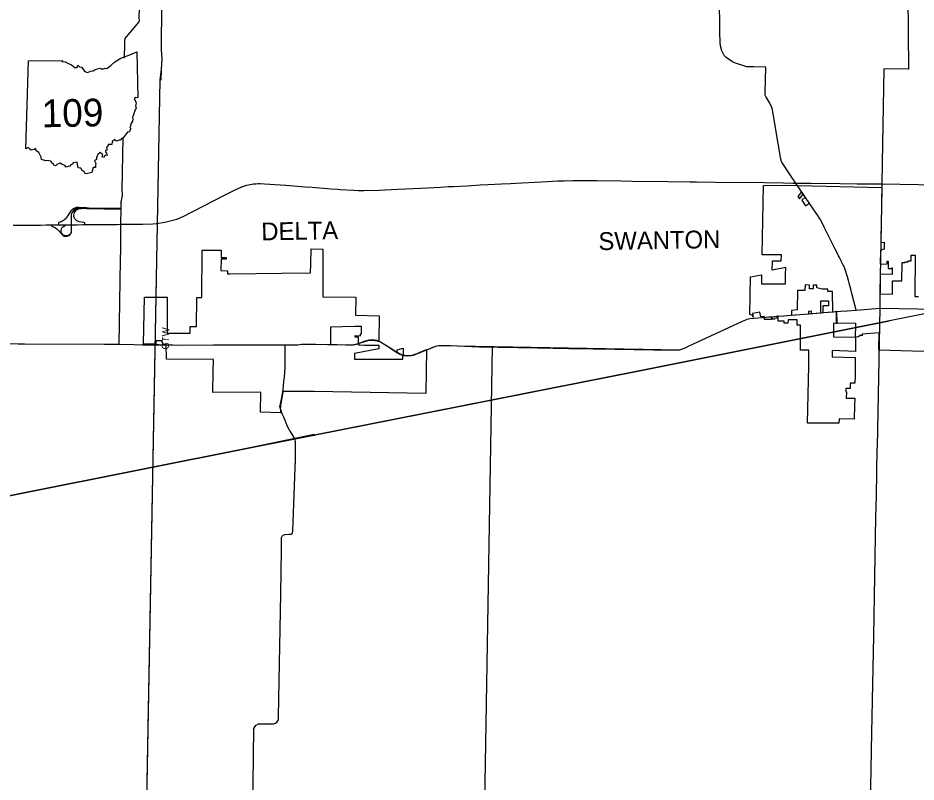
# Model space of a CAD drawing. Extents: x 0 to 849, y 0 to 440.
# Drawn here: x 399.3 to 566.7, y 72.4 to 214.9 of the extents above; entities that cross this region are included whole.
import ezdxf

# ---------------------------------------------------------------- set-up
doc = ezdxf.new("R2010")
doc.units = 0
for name, color, linetype in [('DV_X_Corp_Line', 7, 'Continuous'), ('GM_X_Corporation_Text', 7, 'Continuous'), ('GM_X_County', 7, 'Continuous'), ('GM_X_Interchange_Ramps', 7, 'Continuous'), ('GM_X_Interstate_Route', 7, 'Continuous'), ('PV_P_Walk', 7, 'Continuous'), ('RD_X_RR_2', 7, 'Continuous'), ('SH_Data', 7, 'Continuous')]:
    doc.layers.add(name, color=color, linetype=linetype)

msp = doc.modelspace()

# ---------------------------------------------------------------- linework, layer by layer
at = {"layer": 'DV_X_Corp_Line'}
msp.add_lwpolyline([(568.24, 152.7), (563.91, 152.84), (559.78, 152.94), (559.85, 156.15), (556.66, 155.91), (556.66, 155.63), (556.44, 155.74), (555.9, 155.41), (555.46, 155.4), (555.51, 157.6), (555.51, 157.65), (555.52, 157.94), (551.35, 157.98), (551.32, 155.45), (555.46, 155.4), (555.41, 152.7), (551.08, 152.87), (551.07, 152.28), (551.06, 151.71), (555.39, 151.59), (555.34, 148.1), (555.32, 146.79), (554.42, 146.79), (554.42, 145.79), (553.62, 145.8), (553.6, 145.2), (553.73, 145.19), (553.7, 143.99), (555.28, 143.99), (555.25, 142.68), (555.21, 140.1), (552.36, 140.14), (552.35, 139.36), (546.47, 139.36), (546.73, 150.01), (546.76, 152.92), (545.17, 152.96), (545.2, 157.62), (544.56, 157.61), (544.56, 158.58), (542.85, 158.59), (542.83, 157.98), (542.13, 158), (542.15, 158.35), (541.02, 158.38), (541.02, 159.28), (540.76, 159.26), (540.76, 158.89), (540.35, 158.86), (540.35, 158.71), (539.93, 158.7), (539.93, 159.11), (539.77, 159.11), (539.77, 158.64), (538.47, 158.66), (538.47, 159.25), (537.81, 159.19), (537.57, 160.01), (536.91, 159.91), (536.2, 159.78), (536.34, 159.13), (536.16, 159.46), (535.72, 159.62), (535.85, 166.59), (537.91, 167.01), (537.9, 165.34), (542.35, 165.3), (542.37, 165.81), (542.4, 167.08), (542.43, 168.34), (539.89, 167.84), (539.95, 169.59), (541.6, 169.59), (541.63, 170.72), (538.05, 170.73), (538.29, 183.67), (542.56, 183.71), (542.56, 183.69), (544.72, 183.64), (560.34, 183.27), (560.14, 173.05), (560.78, 173.06), (560.78, 171.77), (560.11, 171.62), (560.06, 168.98), (561.31, 169.02), (561.31, 169.52), (561.53, 169.53), (561.53, 168.17), (562.22, 168.16), (562.22, 168.27), (562.26, 168.27), (562.26, 167.06), (560.03, 167.1), (559.96, 163.42), (562.31, 163.38), (562.32, 165.9), (564.1, 165.9), (564.14, 169.3), (564.68, 169.3), (564.68, 169.41), (565.28, 169.42), (565.28, 169.59), (565.79, 169.59), (565.8, 170.66), (566.53, 170.67), (566.48, 162.95), (567.15, 162.94)], dxfattribs=at)
for points in [[(545.38, 182.48), (544.68, 181.62), (544.97, 181.19), (545.69, 182.03)], [(546.07, 181.46), (545.4, 180.92), (546.09, 179.88), (546.83, 180.35)], [(462.77, 154.2), (462.78, 155.35), (462.12, 155.36), (462.13, 155.68), (463.12, 155.65), (463.14, 155.99), (463.32, 155.99), (463.35, 157.33), (462.16, 157.36), (462.07, 157.36), (457.55, 157.23), (457.52, 154.03), (458.75, 154), (460.63, 153.92), (461.98, 154.01), (462.12, 154.03), (462.72, 154.1), (462.81, 153.95), (462.99, 153.95), (463.01, 153.93), (463.04, 153.93), (463.91, 153.91), (466.53, 153.88), (466.56, 153.19), (462, 152.31), (462.01, 151.26), (471.03, 151.28), (471.03, 152.03), (470.43, 152.27), (470.1, 152.43), (469.97, 152.5), (469.97, 153.02), (471.08, 153.31), (471.07, 152.05), (471.27, 152.01), (471.58, 151.96), (471.92, 151.94), (472.35, 151.95), (472.59, 151.98), (472.99, 152.07), (473.29, 152.16), (474.28, 152.55), (475.47, 153.05), (475.35, 144.89), (457.99, 145.18), (454.5, 145.25), (448.7, 145.23), (448.63, 144.78), (448.49, 144.07), (448.28, 143.03), (448.24, 142.78), (448.21, 142.54), (448.2, 142.32), (448.19, 142.1), (448.21, 141.77), (448.24, 141.55), (448.3, 141.28), (444.47, 141.41), (444.55, 145.11), (435.6, 145.07), (435.69, 148.91), (435.72, 151.18), (426.95, 151.28), (426.94, 154.02), (426.39, 154.02), (426.05, 154.72), (425.01, 154.71), (424.99, 154.04), (422.69, 154.06), (422.89, 162.8), (427.07, 162.81), (427.08, 156.13), (431.41, 156.13), (431.41, 157.37), (432.56, 157.37), (432.65, 162.79), (433.57, 162.76), (433.61, 171.61), (437.19, 171.56), (437.16, 170.2), (438.1, 170.21), (438.11, 169.91), (437.18, 169.9), (437.09, 167.79), (438.35, 167.76), (438.35, 167.17), (438.86, 167.16), (448.42, 167.33), (453.83, 167.37), (453.87, 169), (453.92, 171.81), (456.12, 171.78), (456.11, 162.88), (462.26, 162.85), (462.2, 159.46), (466.63, 159.37), (466.55, 154.62), (466.55, 154.62), (466.39, 154.67), (466.18, 154.73), (466.02, 154.76), (465.8, 154.8), (465.58, 154.82), (465.36, 154.83), (465.14, 154.83), (464.92, 154.82), (464.7, 154.8), (464.49, 154.76), (464.27, 154.71), (464.06, 154.65), (463.75, 154.55), (463.18, 154.34)], [(543.49, 159.48), (546.71, 159.74), (546.7, 160.25), (547.15, 160.3), (547.17, 159.78), (548.96, 159.92), (548.96, 162.16), (550.39, 162.16), (550.39, 161.24), (549.36, 161.24), (549.33, 159.95), (551.21, 160.09), (551.15, 163.87), (550.26, 163.88), (550.26, 164.3), (549.23, 164.35), (548.48, 164.52), (548.23, 164.54), (548.24, 165.07), (547.55, 165.08), (547.54, 164.38), (546.86, 164.39), (546.87, 165.09), (546.02, 165.11), (546, 164.05), (544.62, 164.07), (544.56, 160.44), (543.49, 160.33)], [(551.81, 160.14), (551.81, 158.01), (551.99, 158.01), (551.98, 160.16)]]:
    msp.add_lwpolyline(points, close=True, dxfattribs=at)
at = {"layer": 'GM_X_County'}
msp.add_lwpolyline([(565.21, 219.21), (565.34, 205.31), (565.22, 205.31), (560.72, 205.39), (560.73, 205.24), (560.42, 187.96), (560.42, 187.92), (560.35, 183.93), (560.28, 180.21), (560.26, 179.01), (560.23, 177.46), (560.2, 175.92), (560.18, 174.37), (560.13, 171.84), (560.11, 170.74), (560.1, 170.09), (560.04, 166.44), (559.94, 160.75), (559.44, 135.01), (559.44, 134.96), (559.43, 134.51), (559.27, 125.86), (559.19, 121.81), (558.76, 99.7), (558.41, 81.63), (558.09, 64.89)], dxfattribs=at)
at = {"layer": 'GM_X_Interchange_Ramps'}
for points in [[(405.52, 176.31), (405.53, 176.04), (405.68, 176.01), (406.01, 175.89), (406.29, 175.73), (406.55, 175.54), (406.76, 175.32), (407.5, 174.51), (407.73, 174.31), (407.92, 174.22), (408.16, 174.16), (408.41, 174.17), (408.65, 174.24), (408.83, 174.34), (409.04, 174.52), (409.15, 174.71), (409.23, 174.91), (409.28, 175.13), (409.27, 175.86), (409.26, 176.34), (409.26, 177.87), (409.27, 178.19), (409.35, 178.45), (409.47, 178.69), (409.61, 178.88), (409.8, 179.07), (409.98, 179.19), (410.22, 179.3), (410.49, 179.38), (410.74, 179.4), (411.08, 179.4), (412.08, 179.38), (418.44, 179.26), (418.52, 179.26)], [(412, 179.46), (412, 179.49), (410.65, 179.57), (410.36, 179.57), (410.13, 179.52), (409.86, 179.42), (409.65, 179.32), (409.47, 179.2), (409.31, 179.08), (409.14, 178.9), (409, 178.72), (408.36, 177.73), (408.22, 177.55), (408.06, 177.39), (407.91, 177.24), (407.74, 177.11), (407.54, 176.98), (407.33, 176.87), (407.12, 176.79), (406.88, 176.73), (406.84, 176.72), (406.84, 176.32)], [(418.52, 179.36), (418.42, 179.36), (412.44, 179.45), (412, 179.46), (410.7, 179.48), (410.36, 179.43), (410.15, 179.36), (409.94, 179.25), (409.73, 179.11), (409.55, 178.93), (409.42, 178.75), (409.31, 178.54), (409.22, 178.29), (409.17, 178.04), (409.17, 177.79), (409.19, 176.34), (409.2, 175.19), (409.17, 174.92), (409.08, 174.72), (408.95, 174.54), (408.78, 174.4), (408.58, 174.3), (408.38, 174.24), (408.17, 174.24), (407.93, 174.3), (407.73, 174.41), (407.57, 174.56), (407.46, 174.71), (407.36, 174.9), (407.32, 175.1), (407.32, 175.34), (407.37, 175.52), (407.48, 175.74), (407.63, 175.92), (407.82, 176.05), (408, 176.13), (408.1, 176.15), (408.1, 176.33)], [(411.76, 176.36), (411.76, 176.71), (411.62, 176.72), (411.11, 176.8), (410.71, 176.89), (410.44, 176.97), (410.26, 177.07), (410.07, 177.22), (409.89, 177.44), (409.78, 177.66), (409.72, 177.88), (409.71, 178.1), (409.73, 178.35), (409.8, 178.59), (409.93, 178.82), (410.06, 178.98), (410.21, 179.11), (410.38, 179.22), (410.61, 179.32), (410.78, 179.35), (411.08, 179.35), (411.08, 179.4)]]:
    msp.add_lwpolyline(points, dxfattribs=at)
at = {"layer": 'GM_X_Interstate_Route'}
for p, q in [((560.35, 183.93), (571.18, 183.73)), ((559.94, 160.75), (578.12, 160.49))]:
    msp.add_line(p, q, dxfattribs=at)
for points in [[(419.15, 207.4), (419.18, 210.2), (419.2, 210.64), (419.29, 211.02), (419.53, 211.37), (421.58, 213.8), (421.8, 214.1), (421.91, 214.4), (421.9, 214.92), (421.92, 216.72), (421.89, 219.36)], [(530.16, 212.32), (530.11, 214.87), (530.08, 216.27), (530.04, 218.98)], [(536.45, 205.76), (535.17, 205.79), (532.85, 206.54), (532.52, 206.69), (531.31, 207.48), (530.94, 207.89), (530.51, 208.78), (530.26, 209.66), (530.19, 210.23), (530.16, 212.32), (530.16, 212.32)], [(543.56, 185.16), (543.38, 185.42), (541.68, 187.98), (541.63, 188.1), (541.49, 188.56), (540.47, 194.78), (539.93, 197.84), (539.86, 198.2), (539.48, 198.99), (538.7, 200.24), (538.61, 200.46), (538.56, 200.93), (538.7, 205.71), (536.45, 205.76), (536.45, 205.76)], [(418.69, 181.41), (418.69, 181.41), (418.75, 181.99), (418.72, 182.81), (418.9, 192.6)], [(418.48, 176.42), (419.23, 176.42), (422.47, 176.44), (424.43, 176.5), (425.12, 176.56), (426.68, 176.78), (428.88, 177.4), (430.18, 177.95), (431.48, 178.6), (431.88, 178.79), (437.81, 181.83), (439.8, 182.86), (441.01, 183.4), (441.93, 183.69), (442.57, 183.83), (443.2, 183.93), (443.72, 183.98), (444.06, 184.01), (444.44, 184), (445.24, 183.98), (448.14, 183.75), (449.19, 183.68), (452.84, 183.4), (454.13, 183.31), (457.64, 183.05), (458.91, 182.94), (459.38, 182.91), (461.91, 182.76), (462.7, 182.73), (463.79, 182.7), (466.64, 182.76), (467.7, 182.81), (470.16, 182.95), (474.39, 183.16), (478.08, 183.35), (479.49, 183.43), (480.48, 183.47), (483.01, 183.6), (485.47, 183.75), (486.88, 183.81), (489.43, 183.94), (491.11, 184.03), (493.23, 184.13), (495.67, 184.26), (498.02, 184.38), (499.9, 184.49), (501.12, 184.54), (502.7, 184.59), (505, 184.57), (506.41, 184.55), (507.19, 184.55), (511.73, 184.49), (513.81, 184.47), (520.42, 184.39), (524.58, 184.34), (524.98, 184.34), (525.77, 184.33), (529.3, 184.29), (538.46, 184.18), (541.99, 184.14), (543.74, 184.11), (544.28, 184.1)], [(543.92, 184.63), (543.61, 185.09), (543.56, 185.16)], [(544.48, 183.8), (544.28, 184.1), (543.98, 184.54), (543.92, 184.63)], [(544.28, 184.1), (545.16, 184.1), (547.09, 184.07), (552.55, 184.01), (555.72, 183.97), (558.01, 183.95), (560.35, 183.93)], [(545.29, 182.61), (544.55, 183.71), (544.48, 183.8)], [(545.6, 182.16), (545.29, 182.61)], [(418.48, 176.42), (418.52, 179.26), (418.52, 179.36), (418.53, 179.48), (418.5, 180.27), (418.52, 180.53), (418.54, 180.67), (418.59, 180.88)], [(418.59, 180.88), (418.66, 181.13), (418.69, 181.41)], [(546, 181.57), (545.6, 182.16)], [(547.02, 180.07), (546, 181.57)], [(548.73, 177.53), (548.4, 178.03), (547.55, 179.3), (547.02, 180.07)], [(551.25, 172.54), (549.6, 175.85), (549, 177.07), (548.95, 177.17), (548.88, 177.31), (548.73, 177.53)], [(398.36, 176.25), (400.9, 176.28), (403.46, 176.28), (404.52, 176.3), (405.22, 176.3), (405.52, 176.31), (406.84, 176.32), (408.1, 176.33), (408.8, 176.33), (409.19, 176.34), (409.26, 176.34), (409.61, 176.34)], [(409.61, 176.34), (410.33, 176.34), (411.38, 176.35), (411.76, 176.36), (413, 176.36), (413.56, 176.37), (414.86, 176.39), (415.85, 176.39), (417.79, 176.4), (418.48, 176.42)], [(418.4, 169.79), (418.44, 171.72), (418.48, 176.42)], [(551.64, 171.78), (551.64, 171.78), (551.25, 172.54)], [(553.23, 168.65), (553.22, 168.65), (552.84, 169.42), (552.81, 169.48), (552.42, 170.25), (552.28, 170.52), (552.18, 170.72), (552.17, 170.75), (551.64, 171.78)], [(418.14, 154.05), (418.4, 169.79)], [(553.46, 168.17), (553.23, 168.65)], [(554.11, 165.95), (554.11, 165.95), (553.94, 166.59), (553.47, 168.16), (553.46, 168.17)], [(555.55, 160.43), (555.15, 162.11), (554.77, 163.52), (554.62, 164.05), (554.24, 165.46), (554.11, 165.95)], [(553.86, 160.3), (553.86, 160.3), (555.55, 160.43), (559.94, 160.75)], [(520.42, 152.99), (522.39, 152.96), (522.71, 153), (523.66, 153.41), (524.32, 153.71), (534.34, 158.33), (535, 158.61), (535.21, 158.7), (535.74, 158.85), (538.78, 159.1)], [(538.78, 159.1), (539.3, 159.14)], [(539.3, 159.14), (539.82, 159.18), (540.84, 159.26)], [(540.84, 159.26), (541.09, 159.28), (541.09, 159.28)], [(541.09, 159.28), (542.09, 159.37), (543.3, 159.46)], [(543.3, 159.46), (545.9, 159.68), (546.68, 159.74), (546.9, 159.76), (546.91, 159.76)], [(546.91, 159.76), (547.41, 159.8), (547.42, 159.8)], [(547.42, 159.8), (549.11, 159.93), (549.11, 159.93)], [(549.11, 159.93), (549.45, 159.96), (549.45, 159.96)], [(549.45, 159.96), (551.31, 160.1), (551.31, 160.1)], [(551.31, 160.1), (551.65, 160.13), (551.65, 160.13)], [(551.65, 160.13), (551.82, 160.14), (551.82, 160.14)], [(551.82, 160.14), (552.64, 160.21), (553.81, 160.3), (553.86, 160.3)], [(388.53, 154.24), (399.3, 154.12), (400.49, 154.11), (415.39, 154.05), (418.14, 154.05), (420.96, 154)], [(450.99, 153.97), (451.46, 153.97), (452.17, 154.09), (452.47, 154.09), (452.92, 154.09), (453.6, 154.09), (454.27, 154.08), (454.77, 154.09), (456.98, 154.02), (457.85, 154.01)], [(461.93, 154), (462.09, 154.02), (462.91, 154.23), (463.7, 154.52), (464.33, 154.74), (464.96, 154.86), (465.73, 154.82), (466.27, 154.71), (466.88, 154.48), (468.46, 153.48)], [(420.96, 154), (422.49, 153.96), (422.9, 153.96)], [(422.9, 153.96), (424.83, 153.94)], [(424.83, 153.94), (426.24, 153.93)], [(426.24, 153.93), (426.77, 153.93), (426.77, 153.93)], [(426.77, 153.93), (428.18, 153.92)], [(428.18, 153.92), (429.33, 153.91), (435.75, 153.92)], [(435.75, 153.92), (438.05, 153.92), (440.45, 153.92)], [(440.45, 153.92), (440.71, 153.92), (441.91, 153.92), (442.36, 153.92)], [(442.36, 153.92), (443.76, 153.94)], [(443.76, 153.94), (444.61, 153.94), (445.76, 153.95), (446.83, 153.96), (446.85, 153.96)], [(446.85, 153.96), (446.85, 153.96), (447.02, 153.96), (447.84, 153.96), (449.12, 153.97)], [(448.95, 147.99), (448.95, 147.99), (449.07, 149.67), (449.11, 151.79), (449.12, 152.51), (449.12, 152.55), (449.12, 153.97)], [(449.12, 153.97), (450.76, 153.97), (450.99, 153.97)], [(457.85, 154.01), (458.78, 153.99), (460.38, 153.96), (461.76, 153.97), (461.93, 154)], [(468.46, 153.48), (469.01, 153.14), (470.02, 152.48), (470.1, 152.43)], [(470.1, 152.43), (470.5, 152.21), (471.13, 151.93), (471.22, 151.93)], [(471.22, 151.93), (471.94, 151.89), (472.56, 151.93), (473.05, 152.03), (474.11, 152.46), (475.15, 152.89), (475.59, 153.07)], [(475.59, 153.07), (475.81, 153.16), (476.6, 153.49), (476.9, 153.59), (477.35, 153.73), (477.69, 153.8), (479.94, 153.81)], [(479.94, 153.81), (485.2, 153.56), (488.81, 153.51), (496.15, 153.39), (501.92, 153.29)], [(501.92, 153.29), (501.92, 153.29), (506.53, 153.21), (510.57, 153.14), (517.79, 153.03)], [(517.79, 153.03), (520.42, 152.99), (520.42, 152.99)], [(448.69, 145.19), (448.75, 145.57), (448.87, 147.08), (448.95, 147.99)], [(448.56, 141.11), (448.35, 141.62), (448.15, 142.21), (448.12, 142.42), (448.28, 143.19), (448.63, 144.8), (448.69, 145.19), (448.69, 145.19)], [(448.83, 140.46), (448.56, 141.1), (448.56, 141.11)], [(449.91, 138.05), (449.91, 138.06), (449.54, 138.7), (448.83, 140.46)], [(451, 131.75), (451, 131.75), (451.02, 132.67), (451.03, 135.89), (450.97, 136.23), (450.88, 136.38), (450.76, 136.65), (449.96, 137.96), (449.91, 138.05)], [(449.72, 118.62), (450.04, 118.62), (450.25, 118.65), (450.47, 118.83), (450.51, 119.29), (451.02, 132.67)], [(442.56, 42.75), (442.94, 65.58), (443.12, 72.11), (443.28, 82.45), (443.42, 82.76), (443.66, 83.03), (444.11, 83.29), (446.92, 83.27), (447.31, 83.42), (447.52, 83.6), (447.77, 83.93), (447.84, 84.2), (447.87, 84.67), (448.07, 94.59), (448.18, 100.95), (448.29, 107.57), (448.4, 115.71), (448.42, 118.04), (448.56, 118.27), (448.73, 118.44), (449.01, 118.57), (449.12, 118.6), (449.72, 118.62), (449.73, 118.62)]]:
    msp.add_lwpolyline(points, dxfattribs=at)
at = {"layer": 'PV_P_Walk'}
msp.add_line((400.76, 190.49), (401.22, 206.86), dxfattribs=at)
for points in [[(401.22, 206.86), (407.57, 206.97), (407.47, 206.77), (408.07, 206.73), (408.71, 206.38), (409.25, 206.16), (409.91, 205.63), (410.3, 205.64), (410.47, 206.07), (410.77, 205.74), (411.13, 205.68), (411.75, 204.9), (412.26, 204.73), (412.87, 204.99), (413.33, 205.04), (413.66, 205.3), (414.53, 205.53), (414.78, 205.39), (415.24, 205.42), (415.47, 205.52), (415.87, 205.43), (416.58, 206.03), (417.31, 206.73), (418.43, 207.39), (420.11, 208.02), (421.44, 208.58), (421.63, 200.08)], [(421.63, 200.08), (421.43, 199.97), (421.13, 200.02), (420.92, 199.78), (421.18, 199.39), (421.3, 198.97), (421.19, 198.5), (421.29, 198.12), (421.22, 197.8), (421.03, 197.48), (420.97, 197.18), (420.8, 196.86), (420.82, 196.68), (420.66, 196.54), (420.69, 196.01), (420.61, 195.71), (420.64, 195.46), (420.39, 195.39), (420.44, 195.18), (420.28, 195.02), (420.32, 194.74), (420.14, 194.56), (420.31, 194.21), (420.17, 194.09), (420.05, 193.66), (419.73, 193.57), (419.09, 192.78), (418.86, 192.48), (418.6, 192.41), (418.46, 192.1), (418.14, 192.1), (417.67, 191.88), (417.36, 192.25), (416.82, 191.81), (416.76, 191.3), (416.07, 191.31), (416.1, 191.06), (415.95, 190.98), (415.81, 190.72), (415.89, 190.26), (415.57, 190.15), (415.61, 189.88), (415.81, 189.72), (415.9, 189.21), (415.56, 189.31), (415.28, 188.88), (415, 188.98), (415.09, 189.34), (414.61, 189.78), (414.15, 189.43), (413.91, 188.87), (413.91, 188.49), (413.57, 188.27), (413.79, 187.73), (413.75, 187.37), (413.75, 187.02), (413.33, 187.03), (413.07, 186.09)], [(413.07, 186.09), (412.33, 185.91), (411.81, 185.8), (411.63, 186.23), (411.26, 186.46), (411.02, 186.89), (410.49, 186.94), (410.37, 187.53), (410.31, 188.01), (409.59, 187.9), (409.39, 187.6), (409.13, 187.52), (408.98, 187.23), (408.64, 187.2), (408.26, 187.07), (408.02, 187.35), (407.4, 187.65), (407.13, 187.8), (406.55, 187.56), (406.42, 187.29), (405.96, 187.41), (405.86, 187.72), (405.58, 187.81), (405.52, 188.13), (404.92, 188.31), (404.47, 188.24), (403.67, 188.5), (403.62, 188.93), (403.34, 189.45), (403.2, 189.82), (402.7, 190.09), (402.59, 190.53), (402.43, 190.51), (402.28, 190.34), (401.72, 190.26), (401.49, 190.43), (401.18, 190.73), (400.76, 190.49)]]:
    msp.add_lwpolyline(points, dxfattribs=at)
at = {"layer": 'RD_X_RR_2'}
for q in [(424.21, 154.01), (425.57, 153.98)]:
    msp.add_line((424.89, 154), q, dxfattribs=at)
for points in [[(425.79, 203.33), (426.05, 205.31), (426.17, 207.18), (426.03, 208.99), (426.13, 217.36), (426.11, 219.07), (426.19, 220.8), (426.39, 222.67), (426.87, 224.44), (427.42, 226.13), (428.13, 227.96), (429.14, 229.65), (430.47, 231.38), (432.22, 233.13), (433.83, 234.81), (443.44, 243.65), (451.69, 251.39), (456.64, 255.85)], [(425.97, 203.27), (426.05, 205.31), (426.17, 207.18), (426.03, 208.99), (426.13, 217.36), (426.11, 219.07), (426.19, 220.8), (426.39, 222.67), (426.87, 224.44), (427.42, 226.13), (428.13, 227.96), (429.14, 229.65), (430.47, 231.38), (432.22, 233.13), (433.83, 234.81), (443.44, 243.65), (451.69, 251.39), (456.57, 256), (456.64, 256)], [(423.01, 51.86), (425.8, 203.33)], [(423.39, 72.45), (425.79, 203.33)], [(568.63, 159.76), (514.51, 148.98), (454.53, 137.13), (454.61, 137.13)], [(454.75, 137.17), (514.51, 148.98), (561.79, 158.4)], [(454.53, 137.21), (443.43, 134.93), (399.52, 126.15), (361.72, 118.55), (340.35, 114.29), (340.38, 114.29)], [(340.38, 114.29), (340.35, 114.29), (361.72, 118.55), (399.52, 126.15), (443.43, 134.93), (454.74, 137.17)]]:
    msp.add_lwpolyline(points, dxfattribs=at)
at = {"layer": 'SH_Data'}
msp.add_line((485.83, 40.92), (487.74, 153.62), dxfattribs=at)
msp.add_lwpolyline([(462.77, 154.2), (464.49, 154.76), (465.36, 154.83), (466.27, 154.71), (466.88, 154.48), (468.46, 153.48), (470.1, 152.43), (471.03, 152.03), (471.94, 151.89), (472.56, 151.93), (474.11, 152.46), (475.81, 153.16), (477.35, 153.73), (477.69, 153.8), (522.71, 153)], dxfattribs=at)

# ---------------------------------------------------------------- texts
at = {"layer": 'GM_X_Corporation_Text'}
for s, p in [('DELTA', (444.67, 173.4)), ('SWANTON', (507.53, 171.59))]:
    msp.add_text(s, height=3.325, rotation=1.0142, dxfattribs=at).set_placement(p)
at = {"layer": 'PV_P_Walk'}
msp.add_text('109', height=5.162, rotation=1.0142, dxfattribs=at).set_placement((403.73, 194.49))
at = {"layer": 'RD_X_RR_2'}
msp.add_text('GTW', height=1.33, rotation=88.9488, dxfattribs=at).set_placement((427.41, 153.04))

doc.saveas('drawing.dxf')
